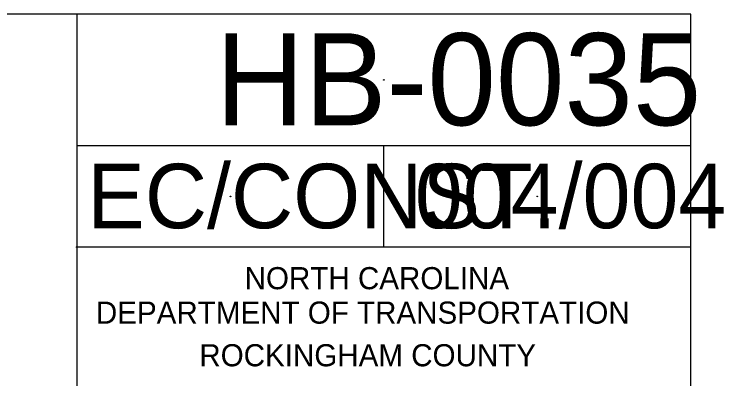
# Model space of a CAD drawing. Extents: x -0.67 to 3.05, y 0 to 1.8.
# Drawn here: x 2.5871 to 2.7798, y 1.6719 to 1.7708 of the extents above; entities that cross this region are included whole.
import ezdxf

# ---------------------------------------------------------------- set-up
doc = ezdxf.new("R2010")
doc.units = 0
for name, color, linetype in [('Exist Environmental Wetland Boundary', 7, 'Continuous'), ('Exist Hydro Stream or Body of Water Cogo Point CELL', 7, 'Continuous'), ('Exist Hydro Swamp or Marsh', 7, 'Continuous'), ('Sheet Plan CELL', 7, 'Continuous')]:
    doc.layers.add(name, color=color, linetype=linetype)

msp = doc.modelspace()

# ---------------------------------------------------------------- linework, layer by layer
at = {"layer": 'Exist Hydro Stream or Body of Water Cogo Point CELL'}
msp.add_lwpolyline([(0.06246, 0.0625), (2.60412, 0.0625), (2.60416, 1.77083), (0.54667, 1.77083), (0.54667, 1.52243), (0.0625, 1.52243)], close=True, dxfattribs=at)
for centre in [(2.6875, 1.75298), (2.64583, 1.72138), (2.72916, 1.72138)]:
    msp.add_circle(centre, 0.0001, dxfattribs=at)
at = {"layer": 'Exist Hydro Swamp or Marsh'}
for p, q in [((2.77083, 1.77083), (0.0625, 1.77083)), ((2.60412, 0.0625), (2.60416, 1.77083)), ((2.77079, 0.0625), (2.77083, 1.77083)), ((2.77083, 1.73513), (2.60416, 1.73513)), ((2.68749, 1.70763), (2.6875, 1.73513)), ((2.77083, 1.70763), (2.60416, 1.70763))]:
    msp.add_line(p, q, dxfattribs=at)
at = {"layer": 'Sheet Plan CELL'}
msp.add_circle((2.60406, 1.70763), 0.0001, dxfattribs=at)
msp.add_circle((2.60406, 1.70763), 0.0001, dxfattribs=at)
msp.add_circle((2.60406, 1.70763), 0.0001, dxfattribs=at)

# ---------------------------------------------------------------- texts
at = {"layer": 'Exist Environmental Wetland Boundary'}
for s, height, p in [('HB-0035', 0.025, (2.64177, 1.74068)), ('EC/CONST.', 0.0175, (2.60697, 1.71273)), ('004/004', 0.0175, (2.69591, 1.71273))]:
    msp.add_text(s, height=height, dxfattribs=at).set_placement(p)
at = {"layer": 'Sheet Plan CELL'}
for s, p in [('NORTH CAROLINA', (2.64968, 1.69618)), ('DEPARTMENT OF TRANSPORTATION', (2.60929, 1.68683)), ('ROCKINGHAM COUNTY', (2.63738, 1.67526))]:
    msp.add_text(s, height=0.0060037, rotation=0, dxfattribs=at).set_placement(p)

doc.saveas('drawing.dxf')
